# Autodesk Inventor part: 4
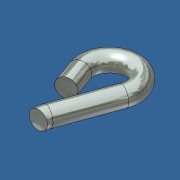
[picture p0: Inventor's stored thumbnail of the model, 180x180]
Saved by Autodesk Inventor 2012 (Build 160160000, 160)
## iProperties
Created: 2013-04
Part Number: 4
Material: Steel
Document SubType Name: Modeling
Designer: Admin
Density: 7.85 g/cm^3
Mass: 3.82737 g
Surface Area: 5.12697 cm^2
Volume: 0.487564 cm^3
Author: Admin
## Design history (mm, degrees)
node "41"
node "4"
node "Base1"
